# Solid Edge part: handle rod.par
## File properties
Title: Handle Rod
Author: Abhinav Rai
Template: Normal.par
Last saved by: CADCIM
Revision: 7
Application: Solid Edge
Density: 0.0000078 kg/mm^3
Accuracy: 0.01
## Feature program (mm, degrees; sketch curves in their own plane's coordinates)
sketch for "unnamed Protrusion 1" plane through (0, 0, 0) normal (0, -1, 0) x-axis (1, 0, 0)
  circle centre (0, 0) radius 3.9624
extrude "unnamed Protrusion 1" add finite 130.175 symmetric
sketch for "ExtrudedCutout_1" plane through (0, 0, 0) normal (0, 0, 1) x-axis (1, 0, 0)
  circle centre (0, 57.4675) radius 1.905
extrude "ExtrudedCutout_1" cut finite 101.6 symmetric
mirror "unnamed Mirror 1" of "ExtrudedCutout_1"
pattern "unnamed Pattern 1"
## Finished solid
Body 1: solid body, 5 faces, 6 edges, 0 vertices.
  Faces by surface: cylinder 3, plane 2
  Edges by curve: intersection 4, circle 2
Bounding box of the edges (mm): 7.925 x 130.175 x 7.925, from (-3.9624, -65.0875, -3.9624) to (3.9624, 65.0875, 3.9624).
Cylindrical faces by radius (mm): R1.905 x2, R3.9624 x1
Planar faces by outward normal: +y 1, -y 1
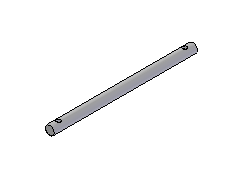
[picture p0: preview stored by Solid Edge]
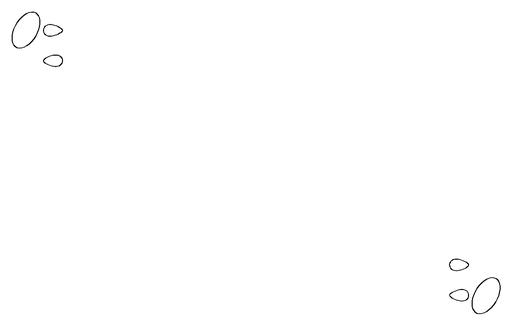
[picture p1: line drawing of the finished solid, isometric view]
